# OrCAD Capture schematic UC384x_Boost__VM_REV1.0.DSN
size A3; title: UC384x_BOOST_Voltage Mode; rev: 1.0
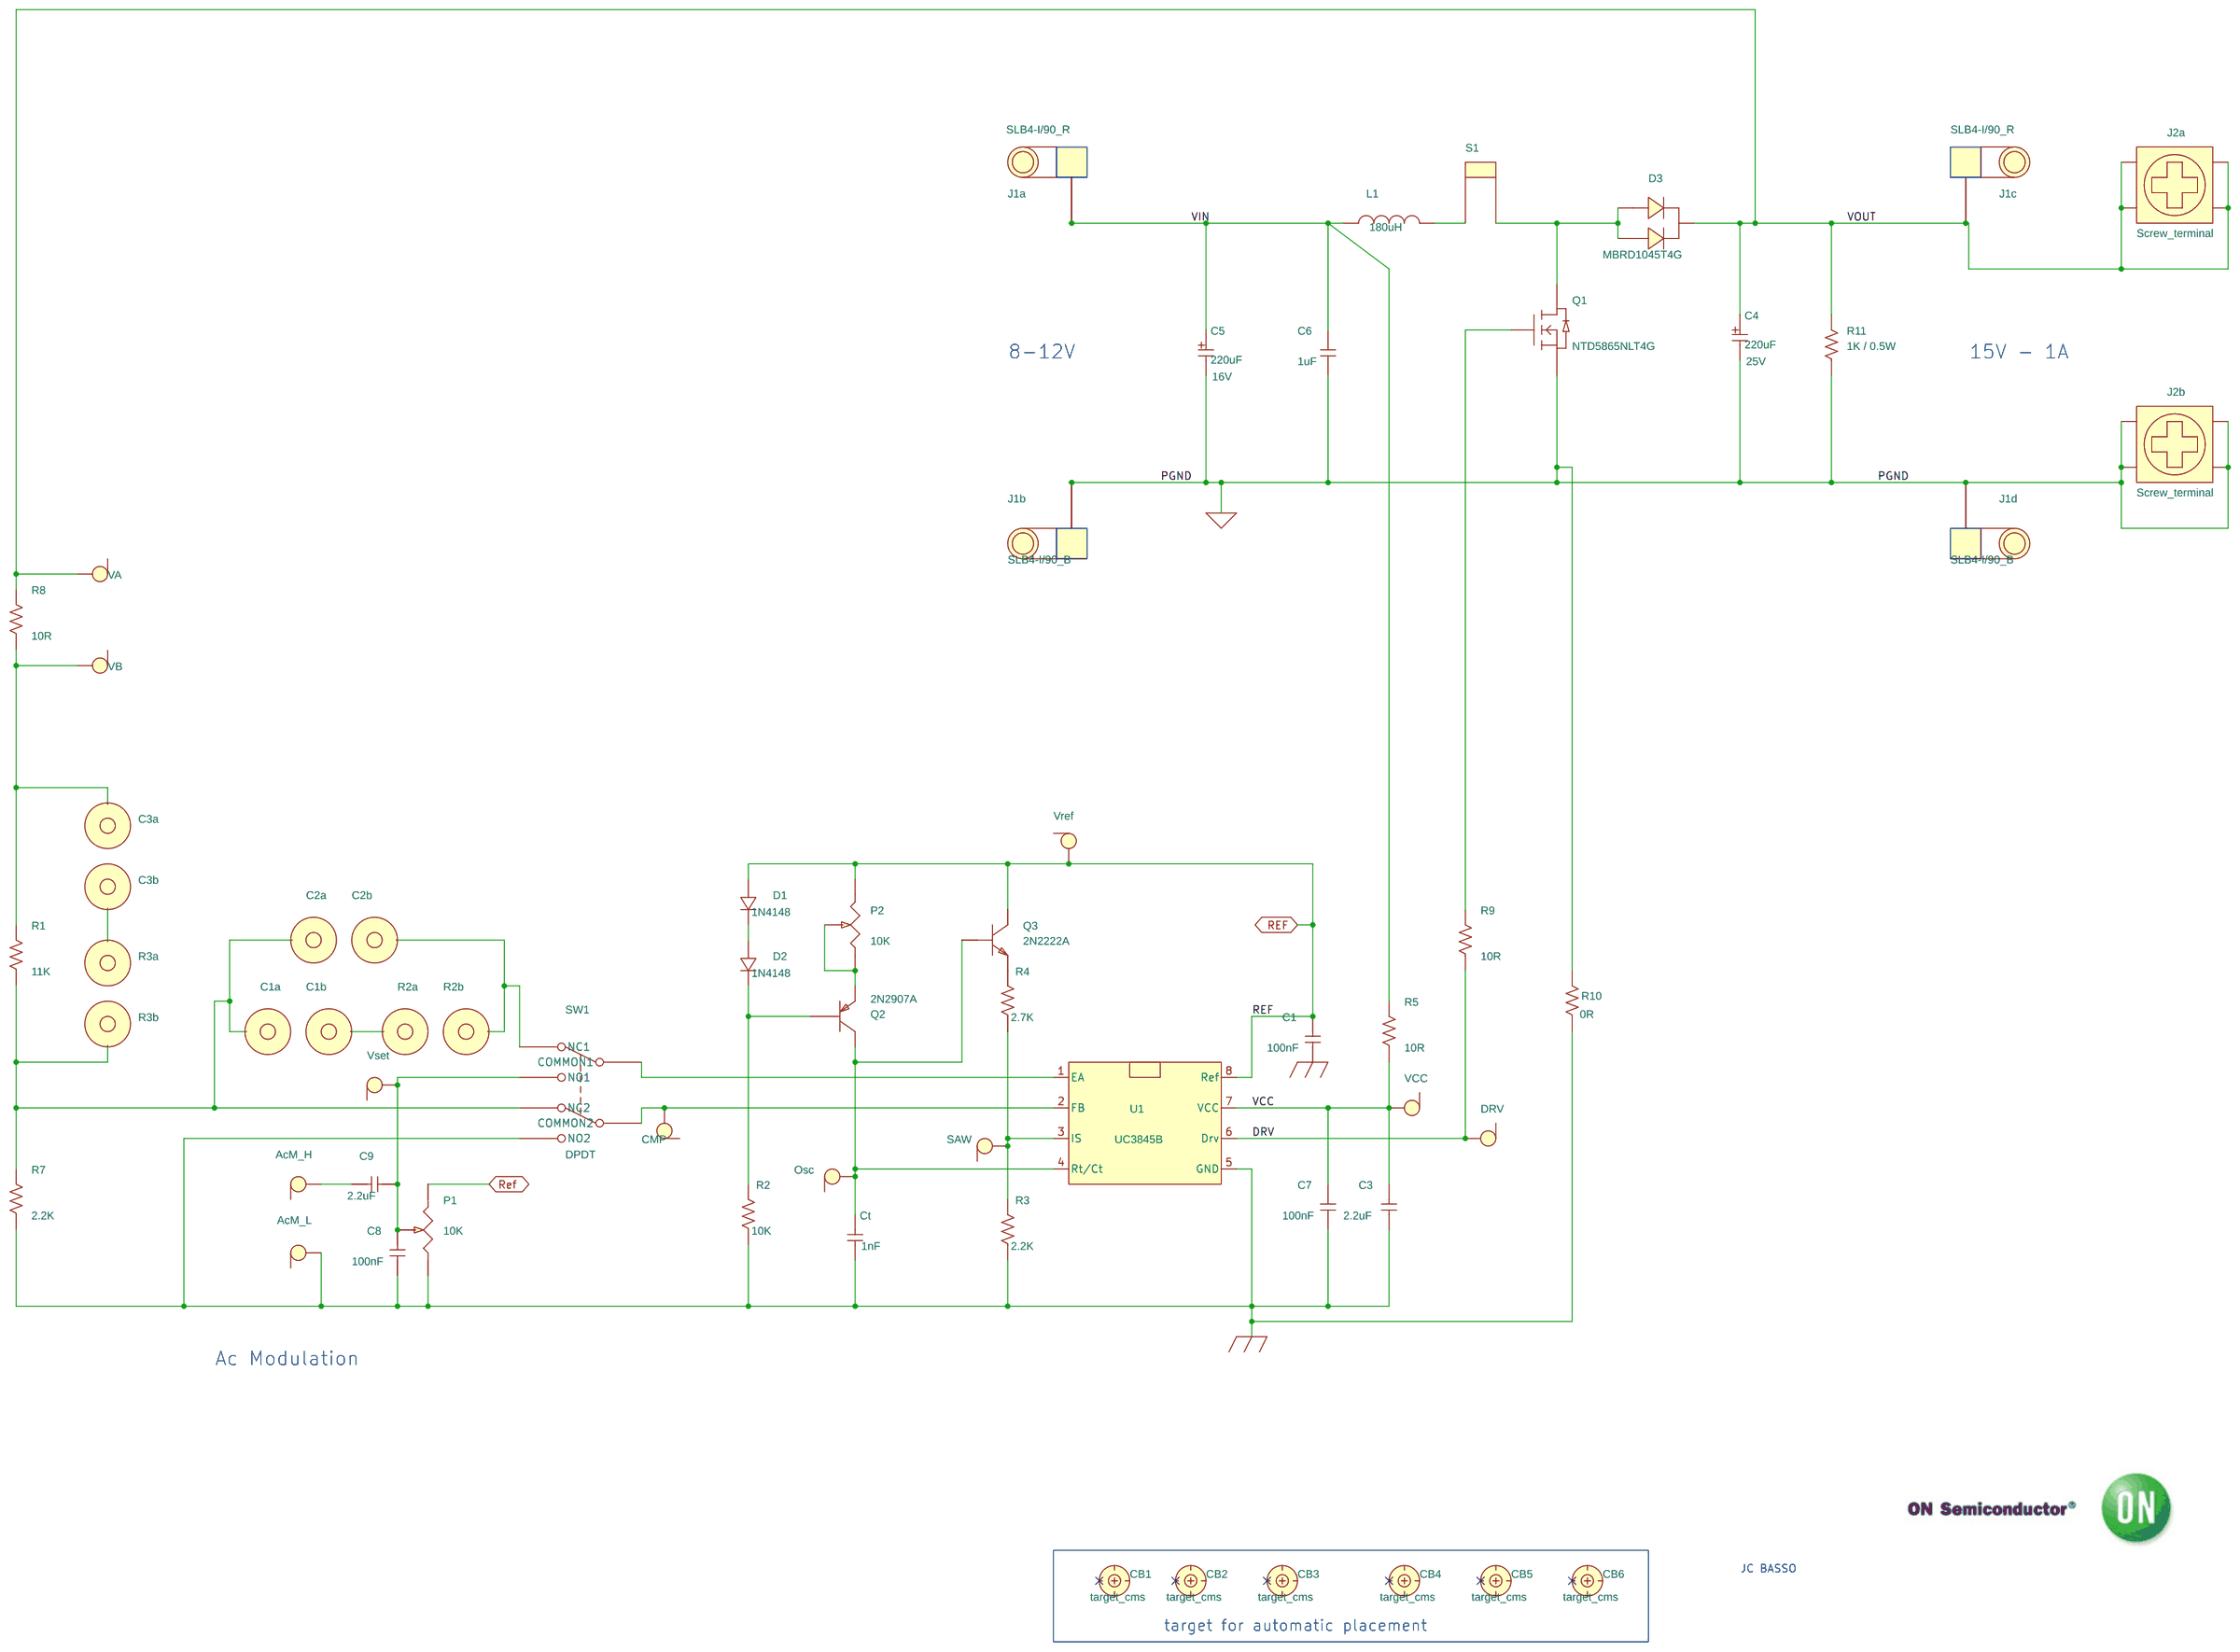
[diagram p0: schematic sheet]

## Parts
AcM_H  TEST POINT  [TP]
AcM_L  TEST POINT  [TP]
C1  100nF  [0805]
C1a  D  [PLOT_5380598-2]
C1b  D  [PLOT_5380598-2]
C2a  D  [PLOT_5380598-2]
C2b  D  [PLOT_5380598-2]
C3  2.2uF  [capa_ch_d5_h11_p2]
C3a  D  [PLOT_5380598-2]
C3b  D  [PLOT_5380598-2]
C4  220uF  [CAPA_ch_D8_H12_P3v5]
C5  220uF  [CAPA_ch_D8_H12_P3v5]
C6  1uF  [0805]
C7  100nF  [0805]
C8  100nF  [0805]
C9  2.2uF  [0805]
CB1  target_cms  [mire_low]
CB2  target_cms  [mire_low]
CB3  target_cms  [mire_low]
CB4  target_cms  [mire_low]
CB5  target_cms  [mire_low]
CB6  target_cms  [mire_low]
CMP  TEST POINT  [TP]
Ct  1nF  [0805]
D1  1N4148  [SOD523]
D2  1N4148  [SOD523]
D3  MBRD1045T4G  [DPAK_TO252]
DRV  TEST POINT  [TP]
J1a  SLB4-I/90_R  [BANANE_4MM_SLB4]
J1b  SLB4-I/90_B  [BANANE_4MM_SLB4]
J1c  SLB4-I/90_R  [BANANE_4MM_SLB4]
J1d  SLB4-I/90_B  [BANANE_4MM_SLB4]
J2a  Screw_terminal  [pc_7701]
J2b  Screw_terminal  [pc_7701]
L1  180uH  [SELF_MSS1210]
Osc  TEST POINT  [TP]
P1  10K  [potar_12t_3266W]
P2  10K  [potar_12t_3266W]
Q1  NTD5865NLT4G  [DPAK_TO252]
Q2  2N2907A  [SOT23]
Q3  2N2222A  [SOT23]
R1  11K  [0805]
R2  10K  [0805]
R2a  D  [PLOT_5380598-2]
R2b  D  [PLOT_5380598-2]
R3  2.2K  [0805]
R3a  D  [PLOT_5380598-2]
R3b  D  [PLOT_5380598-2]
R4  2.7K  [0805]
R5  10R  [0805]
R7  2.2K  [0805]
R8  10R  [0805]
R9  10R  [0805]
R10  0R  [1206]
R11  1K / 0.5W  [RC21U]
S1  Strap  [jumper400h]
SAW  TEST POINT  [TP]
SW1  DPDT  [sw_76SD01ST]
U1  UC3845B  [DIP8_sup]
VA  TEST POINT  [TP]
VB  TEST POINT  [TP]
VCC  TEST POINT  [TP]
Vref  TEST POINT  [TP]
Vset  TEST POINT  [TP]

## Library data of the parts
AcM_H AcM_L CMP DRV Osc SAW VA VB VCC Vref Vset = TEST_POINT_0_v2
C1 C3 C6-C9 Ct = C: COMPFIXED: NO; COMPGROUP: 0; COMPHEIGHT: 0.000; COMPKEY: NO; COMPLOC: [5662.500,337.500]; COMPLOCKED: NO; COMPROT: 270; COMPSIDE: BOT; DECOUPLER: NO; MEMORY: NO; VOLTAGE: 25V
C1a C1b C2a C2b C3a C3b R2a R2b R3a R3b = T_POINT_R_0
C4 = C_elect_0: PART_NUMBER: 1831278; Voltage: 25V
C5 = C_elect_0: PART_NUMBER: 1831278; Voltage: 16V
CB1-CB6 = target_cms
D1 D2 = D1N4148: COMPFIXED: NO; COMPGROUP: 0; COMPHEIGHT: 0.000; COMPKEY: NO; COMPLOC: [2825.000,1450.000]; COMPLOCKED: NO; COMPROT: 90; COMPSIDE: TOP; DECOUPLER: NO; FPLIST: DO35 H; MEMORY: NO; PART_NUMBER: 464-198
D3 = dual_diodeAAK
J1a J1b J1c J1d = HEADER_1_0
J2a J2b = 4_HEADER_0
L1 = L: COMPFIXED: NO; COMPGROUP: 0; COMPHEIGHT: 0.000; COMPKEY: NO; COMPLOC: [6725.000,1075.000]; COMPLOCKED: NO; COMPROT: 270; COMPSIDE: TOP; DECOUPLER: NO; MEMORY: NO; PART_NUMBER: 2211721
P1 P2 = RESISTOR_VAR
Q1 = NMOS_3: PART_NUMBER: IPA50R250CP
Q2 = 2N2907A
Q3 = 2N2222A
R1-R5 R7-R9 = R: COMPFIXED: NO; COMPGROUP: 0; COMPHEIGHT: 0.000; COMPKEY: NO; COMPLOC: [1787.500,750.000]; COMPLOCKED: NO; COMPROT: 90; COMPSIDE: TOP; DECOUPLER: NO; FPLIST: AX/RC05,SM/C_1206H,AX/RC07,AX/RC07_D; MEMORY: NO; VOLTAGE: 200v
R10 = R: ALT_SYMBOLS: RES_1W_D5XL12_jp; COMPFIXED: NO; COMPGROUP: 0; COMPHEIGHT: 0.000; COMPKEY: NO; COMPLOC: [1787.500,750.000]; COMPLOCKED: NO; COMPROT: 90; COMPSIDE: TOP; DECOUPLER: NO; FPLIST: AX/RC05,SM/C_1206H,AX/RC07,AX/RC07_D; MEMORY: NO; VOLTAGE: 200v
R11 = R: COMPFIXED: NO; COMPGROUP: 0; COMPHEIGHT: 0.000; COMPKEY: NO; COMPLOC: [1787.500,750.000]; COMPLOCKED: NO; COMPROT: 90; COMPSIDE: TOP; DECOUPLER: NO; FPLIST: AX/RC05,SM/C_1206H,AX/RC07,AX/RC07_D; MEMORY: NO; PART_NUMBER: NC; VOLTAGE: 200v
S1 = TEST_POINT_0
SW1 = SW_DPDT_SM_0
U1 = UC3845B

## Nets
GND_EARTH: AcM_L.1 C1.2 C3.2 C7.2 C8.2 Ct.2 P1.1(A) R2.1 R3.1 R7.1 R10.1 SW1.2(NO2) U1.5(GND)
GND_SIGNAL: C4.2(-) C5.2(-) C6.2 J1b.1 J1b.2 J1b.3 J1b.4 J1b.5 J1d.1 J1d.2 J1d.3 J1d.4 J1d.5 J2b.1 J2b.2 J2b.3 J2b.4 Q1.3(s) R10.2 R11.1
VCC: C3.1 C7.1 R5.1 U1.7(VCC) VCC.1
VIN: C5.1(+) C6.1 J1a.1 J1a.2 J1a.3 J1a.4 J1a.5 L1.1 R5.2
DRV: DRV.1 R9.1 U1.6(Drv)
REF: C1.1 D1.1 P1.3(B) P2.3(B) Q3.3(COLLECTOR) U1.8(Ref) Vref.1
VOUT: C4.1(+) D3.2(C) J1c.1 J1c.2 J1c.3 J1c.4 J1c.5 J2a.1 J2a.2 J2a.3 J2a.4 R8.2 R11.2 VA.1
N12290274: L1.2 S1.2
N12290314: D3.1(A1) D3.3(A2) Q1.2(d) S1.1
N12292005: Q1.1(g) R9.2
N12295469: Ct.1 Osc.1 Q2.3(COLLECTOR) Q3.2(BASE) U1.4(Rt/Ct)
N12295845: R3.2 R4.1 SAW.1 U1.3(IS)
N12296104: CMP.1 SW1.C2(COMMON2) U1.2(FB)
N12296108: SW1.C1(COMMON1) U1.1(EA)
N12297349: C3b.1(TP) R1.2 R8.1 VB.1
N12298127: C1a.1(TP) C2a.1(TP) R1.1 R3a.1(TP) R7.2 SW1.22(NC2)
N12298463: C8.1 C9.2 P1.2(WIPER) SW1.1(NO1) Vset.1
N12299817: C1b.1(TP) R2a.1(TP)
N12299821: C2b.1(TP) R2b.1(TP) SW1.11(NC1)
N12301916: AcM_H.1 C9.1
N12308692: P2.1(A) P2.2(WIPER) Q2.1(EMITTER)
N12308941: D2.2 Q2.2(BASE) R2.2
N12308973: D1.2 D2.1
N12309768: C3a.1(TP) R3b.1(TP)
N12311633: Q3.1(EMITTER) R4.2

Not connected (* = marked no-connect by the designer): CB1 1*; CB2 1*; CB3 1*; CB4 1*; CB5 1*; CB6 1*

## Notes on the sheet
- 8-12V
- 15V - 1A
- Ac Modulation
- JC BASSO
- target for automatic placement
